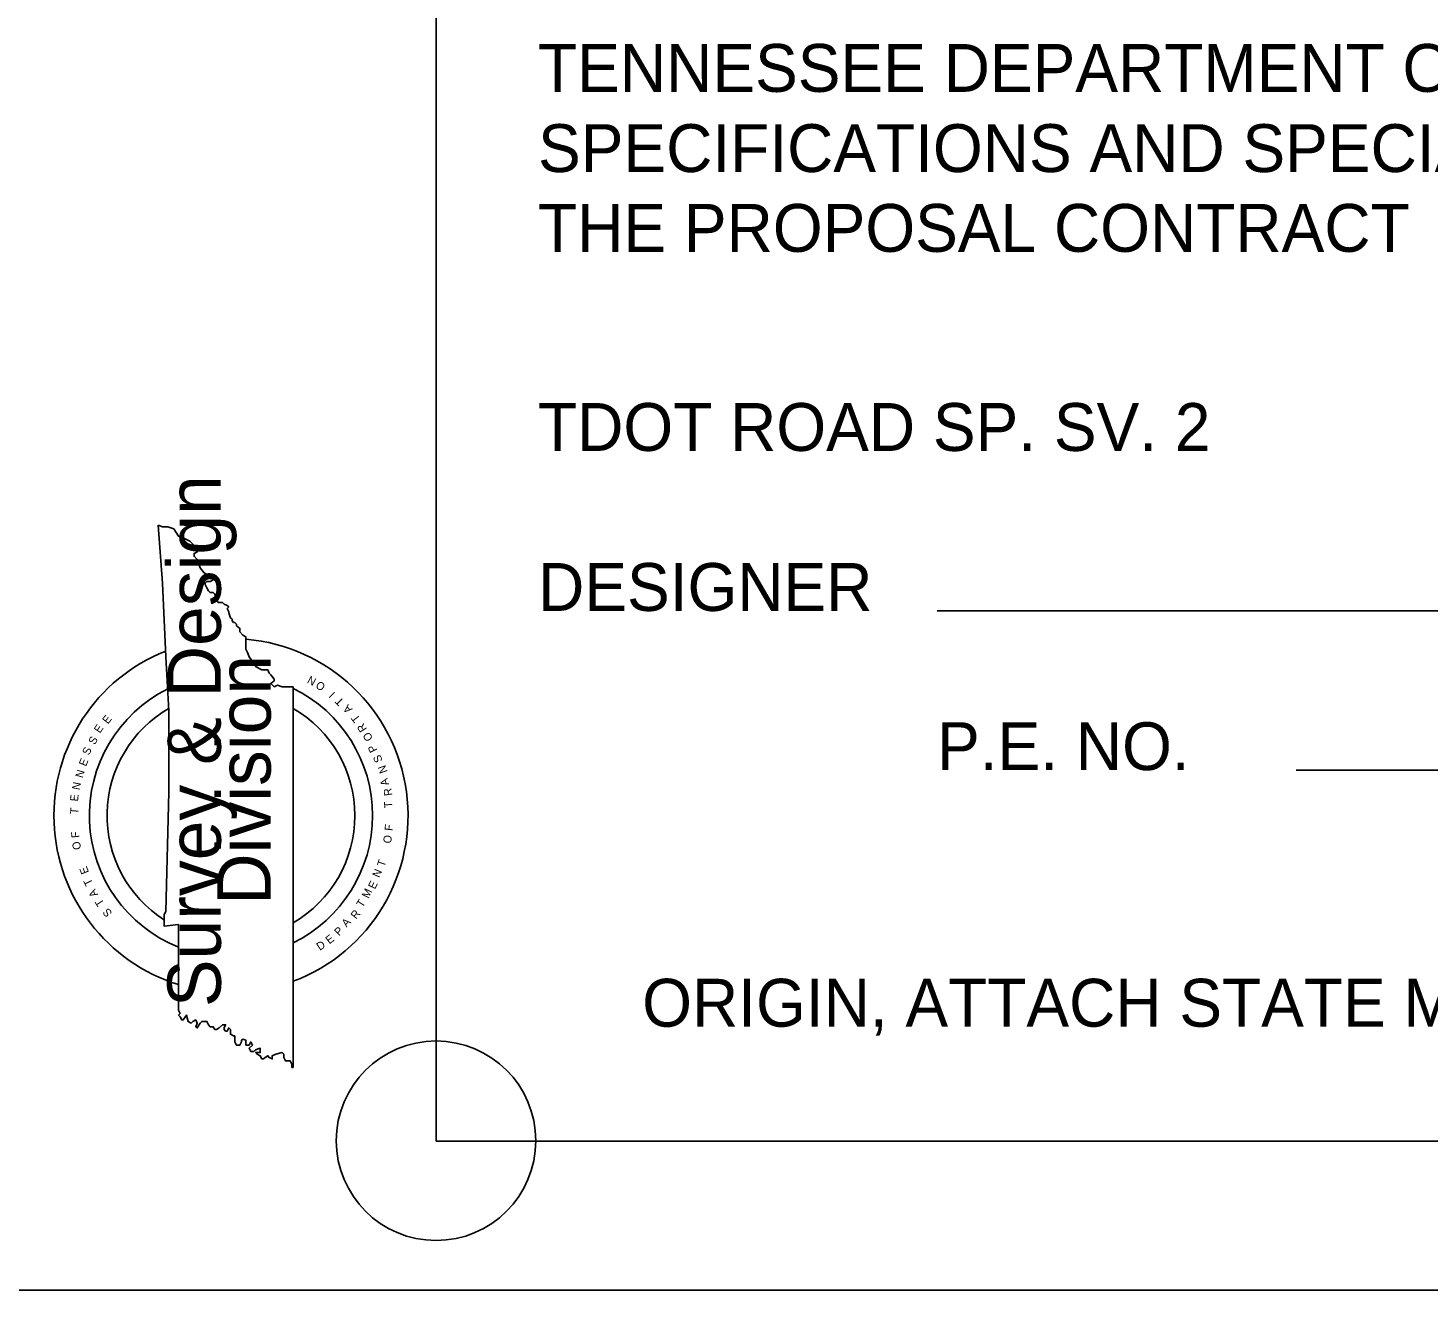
# Model space of a CAD drawing. Extents: x 1623795.1 to 1623879, y 427353.8 to 427391.8.
# Drawn here: x 1623798.056 to 1623801.564, y 427367.862 to 427371.025 of the extents above; entities that cross this region are included whole.
import ezdxf

# ---------------------------------------------------------------- set-up
doc = ezdxf.new("R2010")
doc.units = 0
for name, color, linetype in [('DESIGN - PUBLIC HEARING - Shapes', 7, 'Continuous'), ('DESIGN - SCRATCH - User 1', 7, 'Continuous'), ('DESIGN - SHEET - Corner Text', 7, 'Continuous'), ('DESIGN - SHEET - Light Grid', 7, 'Continuous'), ('DESIGN - SHEET - Linework', 7, 'Continuous')]:
    doc.layers.add(name, color=color, linetype=linetype)

msp = doc.modelspace()

# ---------------------------------------------------------------- linework, layer by layer
at = {"layer": 'DESIGN - PUBLIC HEARING - Shapes'}
msp.add_lwpolyline([(1623799.078, 427389.485), (1623830.562, 427389.485), (1623830.562, 427368.235), (1623799.079, 427368.235)], close=True, dxfattribs=at)
at = {"layer": 'DESIGN - SCRATCH - User 1'}
msp.add_circle((1623799.0784, 427368.2361), 0.25, dxfattribs=at)
at = {"layer": 'DESIGN - SHEET - Corner Text'}
for p, q in [((1623800.334, 427369.564), (1623804.234, 427369.564)), ((1623801.234, 427369.165), (1623807.033, 427369.165))]:
    msp.add_line(p, q, dxfattribs=at)
at = {"layer": 'DESIGN - SHEET - Linework'}
msp.add_line((1623795.063, 427367.862), (1623831.063, 427367.862), dxfattribs=at)
for points in [[(1623799.078, 427389.485), (1623830.562, 427389.485), (1623830.562, 427368.235), (1623799.079, 427368.235), (1623799.079, 427389.236)], [(1623798.382, 427369.779), (1623798.393, 427369.775), (1623798.406, 427369.775), (1623798.421, 427369.77), (1623798.421, 427369.77), (1623798.433, 427369.751), (1623798.445, 427369.747), (1623798.445, 427369.747), (1623798.445, 427369.747), (1623798.453, 427369.743), (1623798.461, 427369.739), (1623798.472, 427369.728), (1623798.48, 427369.728), (1623798.48, 427369.728), (1623798.483, 427369.72), (1623798.483, 427369.72), (1623798.48, 427369.712), (1623798.472, 427369.708), (1623798.472, 427369.708), (1623798.472, 427369.701), (1623798.472, 427369.701), (1623798.48, 427369.693), (1623798.48, 427369.693), (1623798.48, 427369.693), (1623798.48, 427369.693), (1623798.487, 427369.672), (1623798.496, 427369.66), (1623798.508, 427369.652), (1623798.52, 427369.645), (1623798.52, 427369.642), (1623798.52, 427369.642), (1623798.52, 427369.642), (1623798.512, 427369.638), (1623798.504, 427369.638), (1623798.5, 427369.634), (1623798.5, 427369.634), (1623798.5, 427369.634), (1623798.5, 427369.63), (1623798.504, 427369.622), (1623798.504, 427369.622), (1623798.508, 427369.614), (1623798.512, 427369.61), (1623798.52, 427369.61), (1623798.52, 427369.61), (1623798.524, 427369.606), (1623798.524, 427369.606), (1623798.528, 427369.593), (1623798.528, 427369.593), (1623798.532, 427369.585)], [(1623798.433, 427368.563), (1623798.433, 427368.778), (1623798.397, 427368.774), (1623798.397, 427368.803), (1623798.401, 427368.811), (1623798.409, 427369.11), (1623798.409, 427369.314), (1623798.401, 427369.449), (1623798.393, 427369.634), (1623798.382, 427369.779)], [(1623798.532, 427369.585), (1623798.532, 427369.585), (1623798.543, 427369.585), (1623798.547, 427369.581), (1623798.547, 427369.581), (1623798.555, 427369.578), (1623798.559, 427369.574), (1623798.555, 427369.57), (1623798.555, 427369.57), (1623798.559, 427369.562), (1623798.559, 427369.559), (1623798.563, 427369.547), (1623798.567, 427369.543), (1623798.567, 427369.543), (1623798.567, 427369.539), (1623798.571, 427369.535), (1623798.574, 427369.535), (1623798.578, 427369.531), (1623798.578, 427369.527), (1623798.587, 427369.52), (1623798.587, 427369.512), (1623798.594, 427369.503), (1623798.594, 427369.503), (1623798.594, 427369.503), (1623798.602, 427369.499), (1623798.602, 427369.468), (1623798.606, 427369.46), (1623798.606, 427369.46), (1623798.61, 427369.449), (1623798.61, 427369.449), (1623798.618, 427369.437), (1623798.618, 427369.437), (1623798.622, 427369.433), (1623798.626, 427369.429), (1623798.626, 427369.425), (1623798.642, 427369.416), (1623798.642, 427369.416), (1623798.657, 427369.416), (1623798.66, 427369.408), (1623798.664, 427369.404), (1623798.664, 427369.404), (1623798.673, 427369.393), (1623798.673, 427369.393), (1623798.673, 427369.389), (1623798.664, 427369.382), (1623798.664, 427369.382), (1623798.664, 427369.382), (1623798.673, 427369.374), (1623798.673, 427369.374), (1623798.681, 427369.378), (1623798.693, 427369.374), (1623798.701, 427369.374), (1623798.713, 427369.374), (1623798.72, 427369.374)], [(1623798.72, 427369.374), (1623798.72, 427368.42)], [(1623798.614, 427368.46), (1623798.61, 427368.468), (1623798.61, 427368.468), (1623798.618, 427368.476), (1623798.618, 427368.476), (1623798.614, 427368.484), (1623798.61, 427368.476), (1623798.602, 427368.476), (1623798.602, 427368.488), (1623798.602, 427368.488), (1623798.594, 427368.491), (1623798.591, 427368.488), (1623798.591, 427368.488), (1623798.591, 427368.484), (1623798.587, 427368.476), (1623798.578, 427368.476), (1623798.578, 427368.476), (1623798.578, 427368.476), (1623798.574, 427368.484), (1623798.574, 427368.499), (1623798.574, 427368.499), (1623798.571, 427368.499), (1623798.563, 427368.503), (1623798.563, 427368.515), (1623798.563, 427368.515), (1623798.559, 427368.519), (1623798.555, 427368.511), (1623798.551, 427368.511), (1623798.547, 427368.515), (1623798.547, 427368.519), (1623798.551, 427368.527), (1623798.543, 427368.527), (1623798.543, 427368.527), (1623798.535, 427368.519), (1623798.528, 427368.515), (1623798.528, 427368.515), (1623798.524, 427368.515), (1623798.52, 427368.522), (1623798.512, 427368.522), (1623798.508, 427368.527), (1623798.504, 427368.535), (1623798.491, 427368.535), (1623798.487, 427368.531), (1623798.48, 427368.519), (1623798.48, 427368.519), (1623798.476, 427368.522), (1623798.476, 427368.522), (1623798.48, 427368.531), (1623798.48, 427368.531), (1623798.476, 427368.539), (1623798.476, 427368.539), (1623798.469, 427368.535), (1623798.465, 427368.531), (1623798.457, 427368.535), (1623798.457, 427368.535), (1623798.453, 427368.551), (1623798.445, 427368.539), (1623798.441, 427368.539), (1623798.437, 427368.547), (1623798.433, 427368.551), (1623798.433, 427368.551), (1623798.437, 427368.555), (1623798.433, 427368.563), (1623798.433, 427368.563)], [(1623798.72, 427368.42), (1623798.717, 427368.42), (1623798.717, 427368.42), (1623798.717, 427368.424), (1623798.717, 427368.428), (1623798.713, 427368.436), (1623798.701, 427368.436), (1623798.697, 427368.445), (1623798.697, 427368.449), (1623798.697, 427368.453), (1623798.693, 427368.457), (1623798.677, 427368.453), (1623798.668, 427368.449), (1623798.668, 427368.441), (1623798.668, 427368.441), (1623798.668, 427368.441), (1623798.66, 427368.445), (1623798.657, 427368.449), (1623798.65, 427368.445), (1623798.65, 427368.445), (1623798.646, 427368.441), (1623798.642, 427368.441), (1623798.638, 427368.449), (1623798.638, 427368.449), (1623798.63, 427368.453), (1623798.63, 427368.453), (1623798.626, 427368.457), (1623798.626, 427368.457), (1623798.638, 427368.457), (1623798.638, 427368.468), (1623798.638, 427368.468), (1623798.626, 427368.464), (1623798.626, 427368.464), (1623798.626, 427368.464), (1623798.622, 427368.46), (1623798.622, 427368.46), (1623798.614, 427368.46), (1623798.614, 427368.46)]]:
    msp.add_lwpolyline(points, dxfattribs=at)
for radius, start, end in [(0.4437, 290.5761, 85.1103), (0.4437, 111.6407, 252.7624), (0.3549, 116.4861, 248.2585), (0.3549, 296.0602, 63.9398), (0.3106, 119.96, 237.4914), (0.3106, 300.1372, 59.8628)]:
    msp.add_arc((1623798.5644, 427369.0511), radius, start, end, dxfattribs=at)

# ---------------------------------------------------------------- texts
at = {"layer": 'DESIGN - SCRATCH - User 1'}
msp.add_text('ORIGIN, ATTACH STATE MAP (AC=TNMAP)', height=0.119994, dxfattribs=at).set_placement((1623799.595, 427368.522))
at = {"layer": 'DESIGN - SHEET - Light Grid'}
for s, height, p in [('TENNESSEE DEPARTMENT OF TRANSPORTATION DATED MARCH 1, 1995 AND ADDITIONAL', 0.119994, (1623799.334, 427370.865)), ('SPECIFICATIONS AND SPECIAL PROVISIONS CONTAINED IN THE PLANS AND IN', 0.119994, (1623799.334, 427370.664)), ('THE PROPOSAL CONTRACT', 0.119994, (1623799.334, 427370.464)), ('TDOT ROAD SP. SV. 2', 0.119994, (1623799.334, 427369.965)), ('DESIGNER', 0.11999, (1623799.334, 427369.564)), ('P.E. NO.', 0.11999, (1623800.334, 427369.165))]:
    msp.add_text(s, height=height, dxfattribs=at).set_placement(p)
at = {"layer": 'DESIGN - SHEET - Linework'}
for s, height, rotation, p in [('Survey & Design', 0.13386, 90, (1623798.539, 427368.571)), ('Division', 0.13386, 90, (1623798.664, 427368.827)), ('N', 0.02, 151.6992, (1623798.78, 427369.393)), ('O', 0.02, 145.008, (1623798.803, 427369.378)), ('I', 0.02, 135, (1623798.827, 427369.358)), ('T', 0.02, 135, (1623798.849, 427369.338)), ('E', 0.02, 52.125, (1623798.256, 427369.279)), ('A', 0.02, 132.2737, (1623798.87, 427369.318)), ('E', 0.02, 56.3099, (1623798.236, 427369.256)), ('T', 0.02, 128.6598, (1623798.89, 427369.294)), ('R', 0.02, 122.4712, (1623798.906, 427369.268)), ('S', 0.02, 60.2551, (1623798.223, 427369.227)), ('O', 0.02, 118.6105, (1623798.921, 427369.244)), ('S', 0.02, 66.8014, (1623798.209, 427369.201)), ('P', 0.02, 116.565, (1623798.932, 427369.215)), ('S', 0.02, 113.1986, (1623798.945, 427369.189)), ('N', 0.02, 74.0546, (1623798.193, 427369.144)), ('E', 0.02, 68.1986, (1623798.201, 427369.173)), ('N', 0.02, 109.6538, (1623798.957, 427369.161)), ('N', 0.02, 78.6901, (1623798.185, 427369.114)), ('A', 0.02, 105.9454, (1623798.961, 427369.129)), ('E', 0.02, 84.8056, (1623798.181, 427369.086)), ('R', 0.02, 98.7462, (1623798.969, 427369.102)), ('T', 0.02, 85.6013, (1623798.181, 427369.054)), ('T', 0.02, 94.3987, (1623798.969, 427369.071)), ('F', 0.02, 84.2894, (1623798.969, 427369.012)), ('F', 0.02, 95.7106, (1623798.185, 427368.996)), ('O', 0.02, 80.5377, (1623798.965, 427368.98)), ('O', 0.02, 99.4623, (1623798.189, 427368.967)), ('E', 0.02, 111.8014, (1623798.209, 427368.909)), ('N', 0.02, 66.8014, (1623798.936, 427368.894)), ('T', 0.02, 71.5651, (1623798.949, 427368.921)), ('T', 0.02, 116.565, (1623798.219, 427368.881)), ('E', 0.02, 63.435, (1623798.925, 427368.865)), ('A', 0.02, 118.3008, (1623798.232, 427368.853)), ('M', 0.02, 63.435, (1623798.909, 427368.842)), ('T', 0.02, 122.4712, (1623798.248, 427368.831)), ('S', 0.02, 129.8056, (1623798.268, 427368.807)), ('R', 0.02, 51.3402, (1623798.878, 427368.79)), ('T', 0.02, 57.5288, (1623798.894, 427368.819)), ('A', 0.02, 47.7263, (1623798.854, 427368.77)), ('E', 0.02, 37.875, (1623798.811, 427368.728)), ('P', 0.02, 45, (1623798.835, 427368.748)), ('D', 0.02, 33.6901, (1623798.787, 427368.712))]:
    msp.add_text(s, height=height, rotation=rotation, dxfattribs=at).set_placement(p)

doc.saveas('drawing.dxf')
